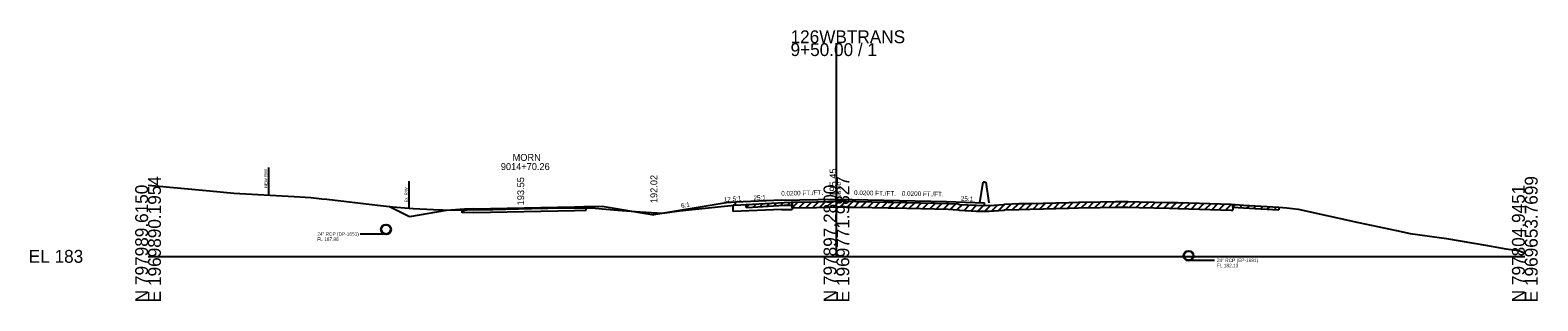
# Model space of a CAD drawing. Extents: x -6494 to 1970605, y -10 to 798140.
# Drawn here: x -25.7 to 302.8, y 1990.3 to 2049.3 of the extents above; entities that cross this region are included whole.
import ezdxf

# ---------------------------------------------------------------- set-up
doc = ezdxf.new("R2010")
doc.units = 0
for name, color, linetype in [('RD_GPK_XS_Cell', 7, 'Continuous'), ('RD_XS_Base', 7, 'Continuous'), ('RD_XS_EarthShd', 7, 'Continuous'), ('RD_XS_ExGround', 7, 'Continuous'), ('RD_XS_ExPaveRet', 7, 'Continuous'), ('RD_XS_ExRW', 7, 'Continuous'), ('RD_XS_MedBWall', 7, 'Continuous'), ('RD_XS_Misc_Line', 7, 'Continuous'), ('RD_XS_NewRW', 7, 'Continuous'), ('RD_XS_Pave', 7, 'Continuous'), ('RD_XS_PaveOvlay', 7, 'Continuous'), ('RD_XS_PaveShd', 7, 'Continuous'), ('RD_XS_Pipe', 7, 'Continuous'), ('RD_XS_TieSlope', 7, 'Continuous'), ('RD_XS_TX_Elev_EX', 7, 'Continuous'), ('RD_XS_TX_Elev_PR', 7, 'Continuous'), ('RD_XS_TX_Misc', 7, 'Continuous'), ('RD_XS_TX_Profile', 7, 'Continuous'), ('RD_XS_TX_ShdSlope', 7, 'Continuous'), ('RD_XS_TX_Slope', 7, 'Continuous'), ('RD_XS_TX_Station', 7, 'Continuous')]:
    doc.layers.add(name, color=color, linetype=linetype)

msp = doc.modelspace()

# ---------------------------------------------------------------- linework, layer by layer
at = {"layer": 'RD_GPK_XS_Cell'}
for p, q in [((150, 2000), (150, 2046.43)), ((0, 2000), (150, 2000)), ((150, 2000), (300, 2000))]:
    msp.add_line(p, q, dxfattribs=at)
at = {"layer": 'RD_XS_Base'}
for p, q in [((94.95, 2010.52), (94.95, 2010.82)), ((127.5, 2011.23), (128, 2011.25)), ((127.5, 2009.75), (127.5, 2011.23)), ((128, 2011.25), (128, 2011.81)), ((68.45, 2009.98), (68.95, 2009.99)), ((68.45, 2009.5), (68.45, 2009.98)), ((70.95, 2009.55), (68.45, 2009.5)), ((68.95, 2009.99), (68.95, 2010.29)), ((92.95, 2010), (95.45, 2010.05)), ((95.45, 2010.53), (94.95, 2010.52)), ((95.45, 2010.05), (95.45, 2010.53)), ((138, 2010.17), (127.5, 2009.75)), ((138, 2010.17), (140.34, 2010.22))]:
    msp.add_line(p, q, dxfattribs=at)
at = {"layer": 'RD_XS_EarthShd'}
for p, q in [((94.95, 2010.82), (98.95, 2010.9)), ((128, 2011.81), (126, 2011.65)), ((68.95, 2010.29), (64.95, 2009.97))]:
    msp.add_line(p, q, dxfattribs=at)
at = {"layer": 'RD_XS_ExGround'}
msp.add_lwpolyline([(0, 2015.48), (13.44, 2014.25), (18.72, 2013.78), (31.87, 2013.04), (35.49, 2012.79), (37.87, 2012.52), (38.97, 2012.44), (49.99, 2011.17), (53.25, 2010.79), (57.79, 2010.4), (59.24, 2010.32), (63.72, 2010.12), (64.24, 2010.12), (66.84, 2010.05), (72.31, 2010.19), (73.2, 2010.18), (73.92, 2010.17), (75.12, 2010.2), (86.42, 2010.5), (87.09, 2010.52), (89.18, 2010.54), (96.7, 2010.59), (98.97, 2010.37), (103.27, 2009.97), (107.21, 2009.71), (112.08, 2009.44), (115.77, 2009.92), (124.85, 2010.87), (127.07, 2011.1), (127.7, 2011.14), (129.14, 2011.2), (130.33, 2011.27), (131.74, 2011.34), (138.6, 2011.75), (140.13, 2011.78), (145.69, 2011.89), (148.27, 2011.95), (150, 2012), (150.63, 2012.02), (152.16, 2011.99), (154.2, 2011.96), (161.29, 2011.81), (162.38, 2011.79), (174.37, 2011.53), (176.52, 2011.41), (176.78, 2011.31), (180.55, 2011.12), (183.27, 2011.09), (186.49, 2011.29), (186.62, 2011.35), (189.71, 2011.48), (192.23, 2011.54), (200.66, 2011.76), (202.75, 2011.8), (207.47, 2011.89), (210.8, 2011.93), (212.62, 2011.95), (213.46, 2011.93), (215.98, 2011.88), (222.48, 2011.74), (224.5, 2011.7), (226.78, 2011.62), (236, 2011.33), (238.68, 2011.18), (246.39, 2010.73), (248.12, 2010.55), (250.58, 2010.27), (263.79, 2007.4), (272.05, 2005.62), (275, 2004.98), (282.96, 2003.87), (291.86, 2002.35), (295.85, 2001.66), (298.67, 2001.24), (300, 2000.69)], dxfattribs=at)
at = {"layer": 'RD_XS_ExPaveRet'}
for p, q in [((130.33, 2010.64), (130.33, 2011.27)), ((130.33, 2010.64), (131.74, 2010.72)), ((131.74, 2010.72), (138.6, 2011.12)), ((138.6, 2011.12), (140.13, 2011.16)), ((140.13, 2011.16), (140.34, 2011.16)), ((140.34, 2010.54), (140.34, 2011.79)), ((140.34, 2011.79), (140.34, 2011.16)), ((140.34, 2010.54), (145.69, 2010.64)), ((145.69, 2010.64), (148.27, 2010.7)), ((148.27, 2010.7), (150, 2010.75)), ((150, 2010.75), (150.63, 2010.77)), ((150.63, 2010.77), (152.16, 2010.74)), ((152.16, 2010.74), (154.2, 2010.71)), ((154.2, 2010.71), (161.29, 2010.56)), ((202.75, 2010.55), (207.47, 2010.64)), ((207.47, 2010.64), (210.8, 2010.68)), ((210.8, 2010.68), (212.62, 2010.7)), ((212.62, 2010.7), (213.46, 2010.68)), ((213.46, 2010.68), (215.98, 2010.63)), ((215.98, 2010.63), (222.48, 2010.49)), ((236.39, 2011.31), (236.39, 2010.06)), ((236.39, 2010.68), (236.39, 2011.31)), ((236.39, 2010.68), (238.68, 2010.55)), ((246.39, 2010.73), (246.39, 2010.1)), ((161.29, 2010.56), (162.38, 2010.54)), ((162.38, 2010.54), (174.37, 2010.28)), ((174.37, 2010.28), (176.52, 2010.16)), ((176.52, 2010.16), (176.78, 2010.06)), ((176.78, 2010.06), (180.55, 2009.87)), ((180.55, 2009.87), (183.27, 2009.84)), ((183.27, 2009.84), (186.49, 2010.04)), ((186.49, 2010.04), (186.62, 2010.1)), ((186.62, 2010.1), (189.71, 2010.23)), ((189.71, 2010.23), (192.23, 2010.29)), ((192.23, 2010.29), (200.66, 2010.51)), ((200.66, 2010.51), (202.75, 2010.55)), ((222.48, 2010.49), (224.5, 2010.45)), ((224.5, 2010.45), (226.78, 2010.37)), ((226.78, 2010.37), (236, 2010.08)), ((236, 2010.08), (236.39, 2010.06)), ((238.68, 2010.55), (246.39, 2010.1))]:
    msp.add_line(p, q, dxfattribs=at)
at = {"layer": 'RD_XS_ExRW'}
msp.add_line((56.82, 2016.36), (56.82, 2010.36), dxfattribs=at)
at = {"layer": 'RD_XS_MedBWall'}
for p, q in [((181.28, 2011.66), (181.94, 2016.14)), ((182.28, 2016.14), (181.94, 2016.14)), ((182.28, 2016.14), (182.61, 2016.14)), ((183.28, 2011.66), (182.61, 2016.14))]:
    msp.add_line(p, q, dxfattribs=at)
at = {"layer": 'RD_XS_Misc_Line'}
for p, q in [((130.33, 2010.64), (131, 2011.3)), ((131.83, 2010.72), (132.5, 2011.39)), ((133.34, 2010.81), (134, 2011.48)), ((134.84, 2010.9), (135.5, 2011.56)), ((136.34, 2010.99), (137, 2011.65)), ((137.84, 2011.08), (138.5, 2011.74)), ((139.34, 2011.14), (139.97, 2011.78)), ((140.34, 2010.54), (141.61, 2011.81)), ((141.84, 2010.57), (143.11, 2011.84)), ((143.34, 2010.59), (144.61, 2011.87)), ((144.84, 2010.62), (146.11, 2011.9)), ((146.34, 2010.66), (147.62, 2011.94)), ((147.84, 2010.69), (149.12, 2011.98)), ((149.34, 2010.73), (150.62, 2012.02)), ((150.84, 2010.76), (152.06, 2011.99)), ((152.34, 2010.73), (153.57, 2011.97)), ((153.84, 2010.72), (155.06, 2011.94)), ((155.34, 2010.69), (156.56, 2011.91)), ((156.84, 2010.65), (158.06, 2011.88)), ((158.34, 2010.62), (159.56, 2011.85)), ((159.84, 2010.59), (161.06, 2011.82)), ((161.34, 2010.56), (162.56, 2011.78)), ((162.84, 2010.53), (164.06, 2011.75)), ((164.34, 2010.49), (165.56, 2011.72)), ((165.84, 2010.46), (167.06, 2011.69)), ((167.34, 2010.43), (168.56, 2011.65)), ((168.84, 2010.4), (170.06, 2011.62)), ((170.34, 2010.37), (171.56, 2011.59)), ((171.84, 2010.33), (173.06, 2011.56)), ((173.34, 2010.3), (174.55, 2011.52)), ((174.84, 2010.25), (176.02, 2011.44)), ((176.34, 2010.17), (177.45, 2011.28)), ((177.84, 2010.01), (179.03, 2011.2)), ((179.34, 2009.93), (180.53, 2011.12)), ((180.84, 2009.87), (182.08, 2011.11)), ((182.34, 2009.85), (183.6, 2011.11)), ((183.84, 2009.88), (185.17, 2011.21)), ((185.34, 2009.97), (186.72, 2011.35)), ((186.84, 2010.11), (188.14, 2011.41)), ((188.34, 2010.17), (189.64, 2011.47)), ((189.84, 2010.23), (191.12, 2011.51)), ((191.34, 2010.27), (192.62, 2011.55)), ((192.84, 2010.31), (194.12, 2011.59)), ((194.34, 2010.35), (195.62, 2011.63)), ((195.84, 2010.38), (197.12, 2011.67)), ((197.34, 2010.42), (198.62, 2011.71)), ((198.84, 2010.46), (200.12, 2011.75)), ((200.34, 2010.5), (201.61, 2011.78)), ((201.84, 2010.53), (203.11, 2011.8)), ((203.34, 2010.56), (204.61, 2011.83)), ((204.84, 2010.59), (206.11, 2011.86)), ((206.34, 2010.62), (207.61, 2011.89)), ((207.84, 2010.64), (209.1, 2011.91)), ((209.34, 2010.66), (210.61, 2011.93)), ((210.84, 2010.68), (212.11, 2011.95)), ((212.34, 2010.7), (213.57, 2011.93)), ((213.84, 2010.68), (215.06, 2011.9)), ((215.34, 2010.64), (216.56, 2011.86)), ((216.84, 2010.61), (218.06, 2011.83)), ((218.34, 2010.58), (219.56, 2011.8)), ((219.84, 2010.54), (221.06, 2011.77)), ((221.34, 2010.51), (222.56, 2011.73)), ((222.84, 2010.48), (224.07, 2011.71)), ((224.34, 2010.45), (225.55, 2011.66)), ((225.84, 2010.4), (227.05, 2011.61)), ((227.34, 2010.35), (228.55, 2011.57)), ((228.84, 2010.31), (230.05, 2011.52)), ((230.34, 2010.26), (231.55, 2011.47)), ((231.84, 2010.21), (233.05, 2011.42)), ((233.34, 2010.16), (234.55, 2011.38)), ((234.84, 2010.12), (236.05, 2011.33)), ((236.39, 2010.68), (236.98, 2011.28)), ((237.89, 2010.6), (238.48, 2011.19)), ((239.39, 2010.51), (239.98, 2011.1)), ((240.89, 2010.42), (241.48, 2011.01)), ((242.39, 2010.34), (242.98, 2010.93)), ((243.89, 2010.25), (244.48, 2010.84)), ((245.39, 2010.16), (245.98, 2010.75))]:
    msp.add_line(p, q, dxfattribs=at)
at = {"layer": 'RD_XS_NewRW'}
msp.add_line((26.26, 2019.36), (26.26, 2013.36), dxfattribs=at)
at = {"layer": 'RD_XS_Pave'}
for p, q in [((81.95, 2010.55), (92.95, 2010.78)), ((138, 2012.21), (150, 2012.45)), ((150, 2012.45), (174, 2011.97)), ((70.95, 2010.33), (81.95, 2010.55)), ((70.95, 2009.55), (81.95, 2009.77)), ((81.95, 2009.77), (92.95, 2010))]:
    msp.add_line(p, q, dxfattribs=at)
at = {"layer": 'RD_XS_PaveOvlay'}
for p, q in [((140.34, 2011.79), (145.69, 2011.89)), ((140.34, 2011.79), (140.34, 2010.22)), ((145.69, 2011.89), (148.27, 2011.95)), ((148.27, 2011.95), (150, 2012)), ((150, 2012), (150.63, 2012.02)), ((150.63, 2012.02), (152.16, 2011.99)), ((152.16, 2011.99), (154.2, 2011.96)), ((154.2, 2011.96), (161.29, 2011.81)), ((161.29, 2011.81), (162.38, 2011.79)), ((162.38, 2011.79), (174.37, 2011.53)), ((174.37, 2011.53), (176.52, 2011.41)), ((176.52, 2011.41), (176.78, 2011.31)), ((176.78, 2011.31), (180.55, 2011.12)), ((180.55, 2011.12), (182.28, 2011.1))]:
    msp.add_line(p, q, dxfattribs=at)
at = {"layer": 'RD_XS_PaveShd'}
for p, q in [((92.95, 2010.78), (94.95, 2010.82)), ((138, 2012.21), (128, 2011.81)), ((174, 2011.97), (182.28, 2011.64)), ((182.28, 2011.1), (182.28, 2011.64)), ((70.95, 2010.33), (68.95, 2010.29))]:
    msp.add_line(p, q, dxfattribs=at)
at = {"layer": 'RD_XS_Pipe'}
for p, q in [((51.19, 2004.86), (46.19, 2004.86)), ((227.41, 1999.13), (232.41, 1999.13))]:
    msp.add_line(p, q, dxfattribs=at)
for centre, radius in [((51.85, 2005.86), 1.1), ((51.85, 2005.86), 1), ((226.74, 2000.13), 1.1), ((226.74, 2000.13), 1)]:
    msp.add_circle(centre, radius, dxfattribs=at)
at = {"layer": 'RD_XS_TieSlope'}
for p, q in [((56.95, 2008.64), (52.46, 2010.88)), ((98.95, 2010.9), (110.22, 2009.02)), ((126, 2011.65), (110.22, 2009.02)), ((64.95, 2009.97), (56.95, 2008.64)), ((110.22, 2009.02), (110.22, 2009.55))]:
    msp.add_line(p, q, dxfattribs=at)

# ---------------------------------------------------------------- texts
at = {"layer": 'RD_GPK_XS_Cell'}
for s, p in [('126WBTRANS', (140, 2046.43)), ('9+50.00 / 1', (140, 2043.63)), ('EL 183', (-26, 1998.6))]:
    msp.add_text(s, height=2.8, dxfattribs=at).set_placement(p)
for s, p in [('E 1969890.1954', (2.8, 1990)), ('E 1969771.9827', (152.8, 1990)), ('E 1969653.7699', (302.8, 1990)), ('N 797989.6150', (0, 1990)), ('N 797897.2800', (150, 1990)), ('N 797804.9451', (300, 1990))]:
    msp.add_text(s, height=2.8, rotation=90, dxfattribs=at).set_placement(p)
at = {"layer": 'RD_XS_ExRW'}
msp.add_text('Ex. R/W ', height=0.65, rotation=90, dxfattribs=at).set_placement((56.57, 2011.74))
at = {"layer": 'RD_XS_NewRW'}
msp.add_text('NEW R/W ', height=0.65, rotation=90, dxfattribs=at).set_placement((25.99, 2014.92))
at = {"layer": 'RD_XS_Pipe'}
for s, p in [('24" RCP (DP-1651)', (36.88, 2004.49)), ('FL 187.86', (36.88, 2003.36)), ('24" RCP (EP-1681)', (232.91, 1998.76)), ('FL 182.13', (232.91, 1997.63))]:
    msp.add_text(s, height=0.75, dxfattribs=at).set_placement(p)
at = {"layer": 'RD_XS_TX_Elev_EX'}
msp.add_text('195.00', height=1, rotation=90, dxfattribs=at).set_placement((151, 2012))
at = {"layer": 'RD_XS_TX_Elev_PR'}
for s, p in [(' 195.45', (150, 2012.45)), (' 193.55', (81.95, 2010.55))]:
    msp.add_text(s, height=1.5, rotation=90, dxfattribs=at).set_placement(p)
at = {"layer": 'RD_XS_TX_Misc'}
msp.add_text('192.02', height=1.5, rotation=90, dxfattribs=at).set_placement((110.97, 2011.6))
at = {"layer": 'RD_XS_TX_Profile'}
for rotation, p in [(2.2906, (131.94, 2012.22)), (357.7094, (177.09, 2012.1))]:
    msp.add_text('25:1', height=1, rotation=rotation, dxfattribs=at).set_placement(p)
at = {"layer": 'RD_XS_TX_ShdSlope'}
msp.add_text('12.5:1', height=1, rotation=4.5739, dxfattribs=at).set_placement((125.5, 2011.86))
at = {"layer": 'RD_XS_TX_Slope'}
for s, rotation, p in [('0.0200 FT./FT.', 1.1458, (137.98, 2013.21)), ('0.0200 FT./FT.', 358.8542, (153.83, 2013.37)), ('0.0200 FT./FT.', 358.8542, (164.24, 2013.22)), ('6:1', 9.4623, (116.22, 2010.53))]:
    msp.add_text(s, height=1, rotation=rotation, dxfattribs=at).set_placement(p)
at = {"layer": 'RD_XS_TX_Station'}
for s, p in [('MORN', (79.44, 2020.8)), ('9014+70.26', (76.87, 2018.8))]:
    msp.add_text(s, height=1.5, dxfattribs=at).set_placement(p)

doc.saveas('drawing.dxf')
